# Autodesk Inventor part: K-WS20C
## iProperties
Created: 2009-07
Part Number: K-WS20C
Document SubType Name: Modeling
Designer: TB
Mass: 32.4644 g
Surface Area: 102.946 cm^2
Volume: 32.4644 cm^3
Density: 1 g/cm^3
Author: TB
